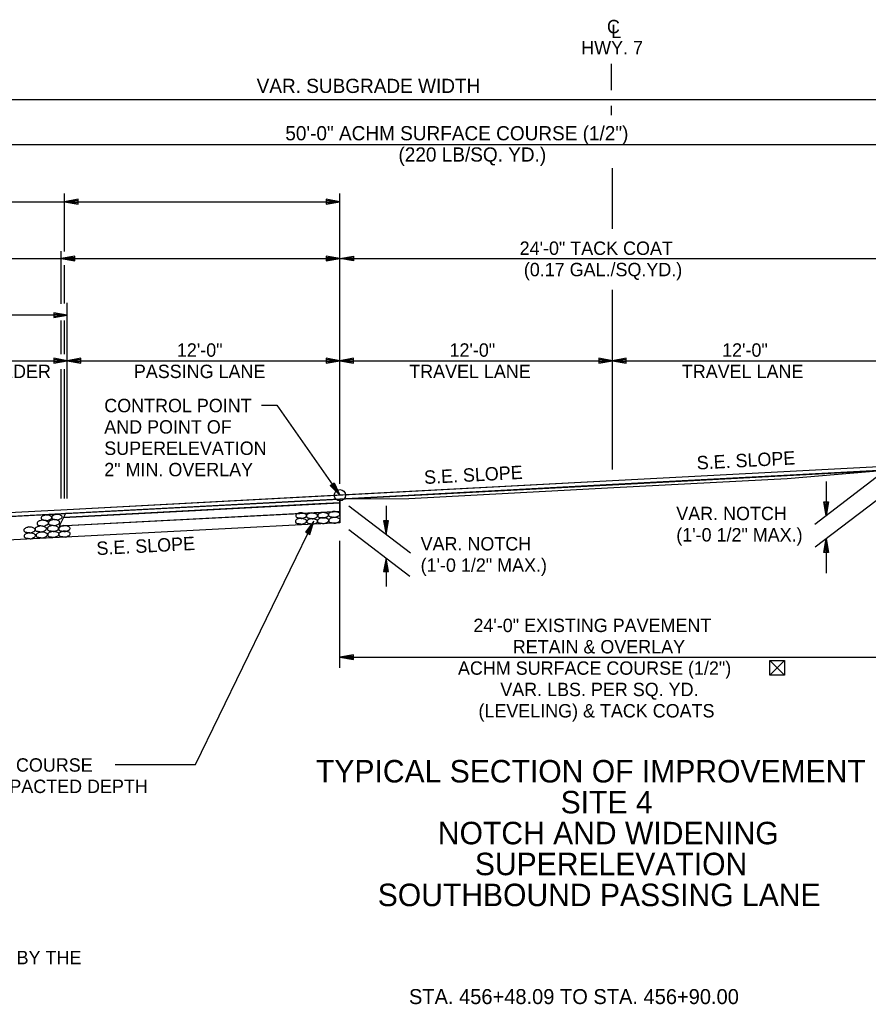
# Model space of a CAD drawing. Extents: x 1398183 to 1398373, y 1967240 to 1968889.
# Drawn here: x 1398232.63 to 1398269.99, y 1967912.34 to 1967955.69 of the extents above; entities that cross this region are included whole.
import ezdxf

# ---------------------------------------------------------------- set-up
doc = ezdxf.new("R2010")
doc.units = 0
for name, color, linetype in [('1', 7, 'Continuous'), ('10', 7, 'Continuous'), ('19', 7, 'Continuous'), ('42', 7, 'Continuous'), ('7', 7, 'Continuous'), ('Level 1', 7, 'Continuous'), ('Level 9', 7, 'Continuous')]:
    doc.layers.add(name, color=color, linetype=linetype)

# ---------------------------------------------------------------- blocks, each defined once
blk = doc.blocks.new('ROCKS')
at = {"layer": '1'}
blk.add_spline([(0.013, 0.06), (0.053, 0.053), (0.107, 0.033), (0.133, 0.013), (0.133, -0.007), (0.12, -0.033), (0.107, -0.04), (0.073, -0.053), (0.033, -0.067), (0.013, -0.067), (-0.02, -0.06), (-0.06, -0.053), (-0.087, -0.047), (-0.113, -0.02), (-0.113, -0.007), (-0.107, 0.02), (-0.087, 0.033), (-0.067, 0.047), (-0.033, 0.053), (-0.02, 0.06), (0.013, 0.06)], degree=3, dxfattribs=at)

msp = doc.modelspace()

# ---------------------------------------------------------------- linework, layer by layer
at = {"layer": '10'}
for p, q in [((1398266.297, 1967927.471), (1398265.656, 1967926.83)), ((1398265.656, 1967927.471), (1398266.297, 1967926.83)), ((1398265.916, 1967926.83), (1398265.905, 1967926.83))]:
    msp.add_line(p, q, dxfattribs=at)
msp.add_lwpolyline([(1398265.905, 1967926.83), (1398265.656, 1967926.83), (1398265.656, 1967927.471), (1398266.297, 1967927.471), (1398266.297, 1967926.83), (1398265.916, 1967926.83)], dxfattribs=at)
at = {"layer": '19'}
for p, q in [((1398222.727, 1967952.173), (1398286.524, 1967952.173)), ((1398278.734, 1967950.173), (1398228.734, 1967950.173)), ((1398216.489, 1967947.673), (1398246.731, 1967947.673)), ((1398234.604, 1967945.482), (1398234.604, 1967948.033)), ((1398235.204, 1967947.778), (1398234.604, 1967947.673)), ((1398234.604, 1967947.673), (1398235.204, 1967947.568)), ((1398235.204, 1967947.723), (1398234.764, 1967947.688)), ((1398234.764, 1967947.658), (1398235.204, 1967947.618)), ((1398235.204, 1967947.568), (1398235.204, 1967947.778)), ((1398246.131, 1967947.779), (1398246.131, 1967947.569)), ((1398246.731, 1967947.673), (1398246.131, 1967947.779)), ((1398246.571, 1967947.688), (1398246.131, 1967947.724)), ((1398246.131, 1967947.569), (1398246.731, 1967947.673)), ((1398246.131, 1967947.619), (1398246.571, 1967947.658)), ((1398246.731, 1967935.25), (1398246.731, 1967948.032)), ((1398234.465, 1967943.174), (1398234.465, 1967945.498)), ((1398217.678, 1967945.173), (1398270.731, 1967945.173)), ((1398235.065, 1967945.278), (1398234.465, 1967945.173)), ((1398234.465, 1967945.173), (1398235.065, 1967945.068)), ((1398235.065, 1967945.223), (1398234.625, 1967945.188)), ((1398234.625, 1967945.158), (1398235.065, 1967945.118)), ((1398235.065, 1967945.068), (1398235.065, 1967945.278)), ((1398246.131, 1967945.279), (1398246.131, 1967945.069)), ((1398246.731, 1967945.173), (1398246.131, 1967945.279)), ((1398246.571, 1967945.188), (1398246.131, 1967945.224)), ((1398246.131, 1967945.069), (1398246.731, 1967945.173)), ((1398246.131, 1967945.119), (1398246.571, 1967945.158)), ((1398246.731, 1967945.173), (1398247.331, 1967945.279)), ((1398247.331, 1967945.069), (1398246.731, 1967945.173)), ((1398246.891, 1967945.188), (1398247.331, 1967945.224)), ((1398247.331, 1967945.119), (1398246.891, 1967945.158)), ((1398247.331, 1967945.279), (1398247.331, 1967945.069)), ((1398234.604, 1967943.193), (1398234.604, 1967944.876)), ((1398234.731, 1967934.614), (1398234.731, 1967943.22)), ((1398234.731, 1967942.673), (1398216.731, 1967942.673)), ((1398234.131, 1967942.779), (1398234.131, 1967942.569)), ((1398234.731, 1967942.673), (1398234.131, 1967942.779)), ((1398234.571, 1967942.688), (1398234.131, 1967942.724)), ((1398234.131, 1967942.569), (1398234.731, 1967942.673)), ((1398234.131, 1967942.619), (1398234.571, 1967942.658)), ((1398234.466, 1967940.955), (1398234.466, 1967942.443)), ((1398234.604, 1967940.958), (1398234.604, 1967942.447)), ((1398234.131, 1967940.779), (1398234.131, 1967940.569)), ((1398234.731, 1967940.673), (1398234.131, 1967940.779)), ((1398234.571, 1967940.688), (1398234.131, 1967940.724)), ((1398235.331, 1967940.778), (1398234.731, 1967940.673)), ((1398235.331, 1967940.723), (1398234.891, 1967940.688)), ((1398235.331, 1967940.568), (1398235.331, 1967940.778)), ((1398246.131, 1967940.779), (1398246.131, 1967940.569)), ((1398246.731, 1967940.673), (1398246.131, 1967940.779)), ((1398246.571, 1967940.688), (1398246.131, 1967940.724)), ((1398247.331, 1967940.778), (1398246.731, 1967940.673)), ((1398247.331, 1967940.723), (1398246.891, 1967940.688)), ((1398247.331, 1967940.568), (1398247.331, 1967940.778)), ((1398258.131, 1967940.779), (1398258.131, 1967940.569)), ((1398258.731, 1967940.673), (1398258.131, 1967940.779)), ((1398258.571, 1967940.688), (1398258.131, 1967940.724)), ((1398259.331, 1967940.778), (1398258.731, 1967940.673)), ((1398259.331, 1967940.723), (1398258.891, 1967940.688)), ((1398259.331, 1967940.568), (1398259.331, 1967940.778)), ((1398228.731, 1967940.673), (1398234.731, 1967940.673)), ((1398234.131, 1967940.569), (1398234.731, 1967940.673)), ((1398234.131, 1967940.619), (1398234.571, 1967940.658)), ((1398234.466, 1967934.614), (1398234.466, 1967940.303)), ((1398234.604, 1967934.614), (1398234.604, 1967940.3)), ((1398234.731, 1967940.673), (1398235.331, 1967940.568)), ((1398234.731, 1967940.673), (1398246.731, 1967940.673)), ((1398234.891, 1967940.658), (1398235.331, 1967940.618)), ((1398246.131, 1967940.569), (1398246.731, 1967940.673)), ((1398246.131, 1967940.619), (1398246.571, 1967940.658)), ((1398246.731, 1967940.673), (1398247.331, 1967940.568)), ((1398246.731, 1967940.673), (1398258.731, 1967940.673)), ((1398246.891, 1967940.658), (1398247.331, 1967940.618)), ((1398258.131, 1967940.569), (1398258.731, 1967940.673)), ((1398258.131, 1967940.619), (1398258.571, 1967940.658)), ((1398258.731, 1967940.673), (1398259.331, 1967940.568)), ((1398258.731, 1967940.673), (1398270.731, 1967940.673)), ((1398258.891, 1967940.658), (1398259.331, 1967940.618)), ((1398270.334, 1967935.537), (1398267.632, 1967933.469)), ((1398246.301, 1967935.18), (1398246.473, 1967935.3)), ((1398246.732, 1967934.749), (1398246.301, 1967935.18)), ((1398246.632, 1967934.873), (1398246.348, 1967935.207)), ((1398246.437, 1967935.271), (1398246.652, 1967934.89)), ((1398246.473, 1967935.3), (1398246.732, 1967934.749)), ((1398268.134, 1967935.353), (1398268.134, 1967933.853)), ((1398234.561, 1967933.774), (1398246.731, 1967934.415)), ((1398245.808, 1967934.368), (1398235.119, 1967933.804)), ((1398246.731, 1967934.415), (1398245.808, 1967934.368)), ((1398246.731, 1967934.581), (1398246.731, 1967934.415)), ((1398246.731, 1967934.415), (1398246.731, 1967934.04)), ((1398246.731, 1967934.04), (1398246.731, 1967934.415)), ((1398247.128, 1967934.278), (1398249.831, 1967932.209)), ((1398248.76, 1967934.278), (1398248.76, 1967933.028)), ((1398270.334, 1967934.51), (1398267.652, 1967932.457)), ((1398268.029, 1967934.453), (1398268.239, 1967934.453)), ((1398268.134, 1967933.853), (1398268.029, 1967934.453)), ((1398268.119, 1967934.013), (1398268.079, 1967934.453)), ((1398268.239, 1967934.453), (1398268.134, 1967933.853)), ((1398268.184, 1967934.453), (1398268.149, 1967934.013)), ((1398246.731, 1967934.04), (1398234.372, 1967933.395)), ((1398234.561, 1967933.774), (1398234.372, 1967933.395)), ((1398234.646, 1967933.944), (1398234.561, 1967933.774)), ((1398245.828, 1967933.993), (1398246.731, 1967934.04)), ((1398246.731, 1967934.04), (1398246.731, 1967933.54)), ((1398240.367, 1967922.901), (1398245.578, 1967933.607)), ((1398245.578, 1967933.607), (1398245.215, 1967933.119)), ((1398245.496, 1967933.471), (1398245.264, 1967933.098)), ((1398245.358, 1967933.049), (1398245.521, 1967933.458)), ((1398245.402, 1967933.026), (1398245.578, 1967933.607)), ((1398248.865, 1967933.628), (1398248.655, 1967933.628)), ((1398248.655, 1967933.628), (1398248.76, 1967933.028)), ((1398248.71, 1967933.628), (1398248.745, 1967933.188)), ((1398248.76, 1967933.028), (1398248.865, 1967933.628)), ((1398248.775, 1967933.188), (1398248.815, 1967933.628)), ((1398245.215, 1967933.119), (1398245.402, 1967933.026)), ((1398247.128, 1967933.236), (1398249.81, 1967931.183)), ((1398246.731, 1967927.148), (1398246.731, 1967932.748)), ((1398268.029, 1967932.225), (1398268.134, 1967932.825)), ((1398268.079, 1967932.225), (1398268.119, 1967932.665)), ((1398268.134, 1967932.825), (1398268.239, 1967932.225)), ((1398268.134, 1967932.825), (1398268.134, 1967931.325)), ((1398268.149, 1967932.665), (1398268.184, 1967932.225)), ((1398268.239, 1967932.225), (1398268.029, 1967932.225)), ((1398248.76, 1967931.987), (1398248.655, 1967931.387)), ((1398248.745, 1967931.827), (1398248.71, 1967931.387)), ((1398248.865, 1967931.387), (1398248.76, 1967931.987)), ((1398248.76, 1967931.987), (1398248.76, 1967930.737)), ((1398248.815, 1967931.387), (1398248.775, 1967931.827)), ((1398248.655, 1967931.387), (1398248.865, 1967931.387)), ((1398247.331, 1967927.723), (1398246.731, 1967927.618)), ((1398247.331, 1967927.513), (1398247.331, 1967927.723)), ((1398246.731, 1967927.618), (1398247.331, 1967927.513)), ((1398246.731, 1967927.618), (1398270.731, 1967927.618)), ((1398247.331, 1967927.668), (1398246.891, 1967927.633)), ((1398246.891, 1967927.603), (1398247.331, 1967927.563)), ((1398236.838, 1967922.901), (1398240.367, 1967922.901))]:
    msp.add_line(p, q, dxfattribs=at)
for points in [[(1398243.284, 1967938.712), (1398243.949, 1967938.712), (1398246.731, 1967934.749)], [(1398278.731, 1967936.446), (1398270.731, 1967936.022), (1398258.731, 1967935.386), (1398246.731, 1967934.75), (1398234.731, 1967934.114), (1398228.731, 1967933.796)], [(1398278.813, 1967936.284), (1398270.731, 1967935.855), (1398258.731, 1967935.219), (1398246.731, 1967934.583), (1398234.731, 1967933.947), (1398228.731, 1967933.629)], [(1398234.372, 1967933.395), (1398234.94, 1967933.426), (1398245.828, 1967933.993)], [(1398235.119, 1967933.804), (1398234.561, 1967933.774), (1398234.372, 1967933.395)], [(1398246.731, 1967933.54), (1398234.372, 1967932.895), (1398222.693, 1967932.287)]]:
    msp.add_lwpolyline(points, dxfattribs=at)
for points in [[(1398228.646, 1967933.626), (1398234.646, 1967933.944), (1398258.722, 1967935.214), (1398270.817, 1967935.852), (1398278.813, 1967936.284), (1398278.731, 1967936.446), (1398270.731, 1967936.022), (1398258.731, 1967935.386), (1398234.731, 1967934.114), (1398228.731, 1967933.796)], [(1398234.646, 1967933.944), (1398234.561, 1967933.774), (1398235.37, 1967933.816), (1398244.213, 1967934.282), (1398246.731, 1967934.415), (1398246.731, 1967934.581), (1398245.573, 1967934.52), (1398235.312, 1967933.979)]]:
    msp.add_lwpolyline(points, close=True, dxfattribs=at)
at = {"layer": '42'}
msp.add_lwpolyline([(1398270.731, 1967935.841), (1398266.421, 1967935.468), (1398258.785, 1967935.079), (1398249.763, 1967934.595), (1398246.74, 1967934.584), (1398246.731, 1967934.583)], dxfattribs=at)
at = {"layer": '7'}
for p, q in [((1398258.689, 1967952.585), (1398258.689, 1967953.742)), ((1398258.689, 1967951.479), (1398258.689, 1967951.891)), ((1398258.731, 1967946.48), (1398258.731, 1967949.154)), ((1398258.731, 1967935.886), (1398258.731, 1967943.795))]:
    msp.add_line(p, q, dxfattribs=at)
at = {"layer": 'Level 9'}
msp.add_circle((1398246.731, 1967934.749), 0.25, dxfattribs=at)

# ---------------------------------------------------------------- block references
at = {"layer": 'Level 1'}
for p, xscale, yscale, rotation in [((1398233.794, 1967933.766), 1.8771740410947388, 1.8771740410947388, 1.8263814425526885), ((1398234.253, 1967933.794), 1.849824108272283, 1.849824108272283, 1.826381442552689), ((1398245.007, 1967933.861), 1.907051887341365, 1.9070518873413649, -0.173618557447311), ((1398245.483, 1967933.85), 1.9598639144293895, 1.959863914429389, -0.173618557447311), ((1398245.968, 1967933.64), 2.011654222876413, 2.011654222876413, 1.8263814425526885), ((1398245.97, 1967933.876), 1.9008744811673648, 1.900874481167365, 1.8263814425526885), ((1398246.458, 1967933.913), 2.011654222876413, 2.011654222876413, 1.8263814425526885), ((1398246.464, 1967933.655), 2.011654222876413, 2.011654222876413, 1.8263814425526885), ((1398233.047, 1967933.229), 2.011654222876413, 2.011654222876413, 1.8263814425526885), ((1398233.543, 1967933.275), 2.011654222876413, 2.011654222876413, 1.8263814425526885), ((1398233.628, 1967933.528), 2.011654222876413, 2.011654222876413, 1.8263814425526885), ((1398234.079, 1967933.292), 2.011654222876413, 2.011654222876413, 1.8263814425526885), ((1398234.124, 1967933.553), 2.011654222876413, 2.011654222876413, 1.8263814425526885), ((1398234.124, 1967933.553), 2.011654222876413, 2.011654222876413, 1.8263814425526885), ((1398234.581, 1967933.288), 2.011654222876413, 2.011654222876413, 1.8263814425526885), ((1398244.997, 1967933.614), 1.9974694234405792, 1.9974694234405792, -0.17361855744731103), ((1398245.494, 1967933.605), 1.890205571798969, 1.8902055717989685, -0.17361855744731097), ((1398233.062, 1967932.971), 2.011654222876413, 2.011654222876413, 1.8263814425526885), ((1398233.585, 1967933.01), 2.011654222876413, 2.011654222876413, 1.8263814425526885), ((1398234.096, 1967933.032), 2.011654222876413, 2.011654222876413, 1.8263814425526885), ((1398234.589, 1967933.046), 2.011654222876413, 2.011654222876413, 1.8263814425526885)]:
    msp.add_blockref('ROCKS', p, dxfattribs=dict(at, xscale=xscale, yscale=yscale, rotation=rotation))

# ---------------------------------------------------------------- texts
at = {"layer": '10'}
for s, height, p in [('12\'-0"', 0.59, (1398239.554, 1967940.848)), ('12\'-0"', 0.59, (1398251.554, 1967940.848)), ('12\'-0"', 0.59, (1398263.554, 1967940.848)), ('SHOULDER', 0.59, (1398229.624, 1967939.908)), ('PASSING LANE', 0.59001, (1398237.66, 1967939.908)), ('TRAVEL LANE', 0.59001, (1398249.781, 1967939.908)), ('TRAVEL LANE', 0.59001, (1398261.781, 1967939.908)), ('CONTROL POINT', 0.59001, (1398236.357, 1967938.405)), ('AND POINT OF ', 0.59001, (1398236.357, 1967937.465)), ('SUPERELEVATION', 0.59001, (1398236.357, 1967936.525)), ('2" MIN. OVERLAY', 0.59001, (1398236.357, 1967935.585)), ('VAR. NOTCH', 0.59, (1398261.536, 1967933.653)), ('VAR. NOTCH', 0.59, (1398250.283, 1967932.319)), ('(1\'-0 1/2" MAX.)', 0.59001, (1398261.536, 1967932.713)), ('(1\'-0 1/2" MAX.)', 0.59001, (1398250.283, 1967931.379))]:
    msp.add_text(s, height=height, dxfattribs=at).set_placement(p)
for s, rotation, p in [('24\'-0" EXISTING PAVEMENT', 0, (1398252.607, 1967928.726)), ('RETAIN & OVERLAY', 0, (1398254.338, 1967927.786)), ('ACHM SURFACE COURSE (1/2")', 0, (1398251.927, 1967926.846)), ('VAR. LBS. PER SQ. YD.', 0, (1398253.79, 1967925.906)), ('(LEVELING) & TACK COATS', 0, (1398252.828, 1967924.966)), ('TO BE USED IF AND WHERE DIRECTED BY THE ', 360, (1398217.287, 1967914.102))]:
    msp.add_text(s, height=0.59001, rotation=rotation, dxfattribs=at).set_placement(p)
at = {"layer": '19'}
for s, height, p in [('C', 0.59, (1398258.484, 1967955.088)), ('L', 0.59, (1398258.672, 1967954.877)), ('HWY. 7', 0.59, (1398257.353, 1967954.158)), ('VAR. SUBGRADE WIDTH', 0.625, (1398243.065, 1967952.46)), ('50\'-0" ACHM SURFACE COURSE (1/2")', 0.625, (1398244.327, 1967950.376)), ('(220 LB/SQ. YD.)', 0.625, (1398249.307, 1967949.439)), ('TYPICAL SECTION OF IMPROVEMENT', 0.98999, (1398245.678, 1967922.105)), ('SITE 4', 0.99, (1398256.447, 1967920.744)), ('NOTCH AND WIDENING', 0.98999, (1398251.041, 1967919.383)), ('SUPERELEVATION', 0.98999, (1398252.67, 1967918.022)), ('SOUTHBOUND PASSING LANE', 0.98999, (1398248.395, 1967916.66)), ('STA. 456+48.09 TO STA. 456+90.00', 0.65999, (1398249.769, 1967912.348))]:
    msp.add_text(s, height=height, dxfattribs=at).set_placement(p)
for s, height, rotation, p in [('S.E. SLOPE', 0.59, 3.0338, (1398262.452, 1967935.879)), ('S.E. SLOPE', 0.59, 3.0338, (1398250.452, 1967935.243)), ('S.E. SLOPE', 0.59, 3.0338, (1398236.029, 1967932.113)), ('AGGREGATE BASE COURSE', 0.59001, 360, (1398224.929, 1967922.58)), ('(CLASS 7) - 6" COMPACTED DEPTH', 0.59001, 360, (1398224.929, 1967921.64))]:
    msp.add_text(s, height=height, rotation=rotation, dxfattribs=at).set_placement(p)
at = {"layer": '42'}
for s, p in [('24\'-0" TACK COAT', (1398254.642, 1967945.331)), ('(0.17 GAL./SQ.YD.)', (1398254.826, 1967944.391))]:
    msp.add_text(s, height=0.59001, rotation=360, dxfattribs=at).set_placement(p)

doc.saveas('drawing.dxf')
